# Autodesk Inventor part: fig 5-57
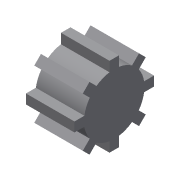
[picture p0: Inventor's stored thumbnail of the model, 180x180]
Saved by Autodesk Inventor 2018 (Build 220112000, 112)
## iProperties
Created: 2005-12
Part Number: fig 5-57
Document SubType Name: Modeling
Designer: CADCIM
Density: 1 g/cm^3
Material: Generic
Appearance: Default
Author: CADCIM
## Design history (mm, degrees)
sketch "Sketch1"
  geometry: C1 r 27.506 at (0, 0)
  constraints: 1 centre point
extrude "Extrusion1" new body sketch "Sketch1" distance "d0" = 20; taper "d1" = 0 deg
sketch "Sketch2"
  geometry: L1 (-12.302, -1.705)-(-16.396, -1.705); L2 (-16.396, -1.705)-(-16.396, 2.216); L3 (-16.396, 2.216)-(-12.302, 2.216); L4 (-7.311, -9.833)-(-10.206, -12.728); L5 (-10.206, -12.728)-(-12.979, -9.955); L6 (-12.979, -9.955)-(-10.084, -7.06); L7 (1.966, -12.051)-(1.966, -16.145); L8 (1.966, -16.145)-(-1.956, -16.145); L9 (-1.956, -16.145)-(-1.956, -12.051); L10 (10.093, -7.06)-(12.988, -9.955); L11 (12.988, -9.955)-(10.215, -12.728); L12 (10.215, -12.728)-(7.32, -9.833); L13 (12.311, 2.216)-(16.405, 2.216); L14 (16.405, 2.216)-(16.405, -1.705); L15 (16.405, -1.705)-(12.311, -1.705); L16 (7.32, 10.344)-(10.215, 13.239); L17 (10.215, 13.239)-(12.988, 10.466); L18 (12.988, 10.466)-(10.093, 7.571); L19 (-1.956, 12.562)-(-1.956, 16.656); L20 (-1.956, 16.656)-(1.966, 16.656); L21 (1.966, 16.656)-(1.966, 12.562); L22 (-10.084, 7.571)-(-12.979, 10.466); L23 (-12.979, 10.466)-(-10.206, 13.239); L24 (-10.206, 13.239)-(-7.311, 10.344); A1 r 12.462 centre (0.005, 0.256) between (-12.302, -1.705) and (-10.084, -7.06); A2 r 12.462 centre (0.005, 0.256) between (-7.311, -9.833) and (-1.956, -12.051); A3 r 12.462 centre (0.005, 0.256) between (1.966, -12.051) and (7.32, -9.833); A4 r 12.462 centre (0.005, 0.256) between (10.093, -7.06) and (12.311, -1.705); A5 r 12.462 centre (0.005, 0.256) between (12.311, 2.216) and (10.093, 7.571); A6 r 12.462 centre (0.005, 0.256) between (7.32, 10.344) and (1.966, 12.562); A7 r 12.462 centre (0.005, 0.256) between (-1.956, 12.562) and (-7.311, 10.344); A8 r 12.462 centre (0.005, 0.256) between (-10.084, 7.571) and (-12.302, 2.216)
  constraints: 48 end point, 16 point on circle, 8 centre point, 2 parallel, 1 horizontal, 1 perpendicular, 57 other
  dimensions: "d4" = 360 deg dimension on A1.centre L2.end (derived)
extrude "Extrusion2" sketch "Sketch2" distance "d6" = 20; taper "d7" = 0 deg
body "Solid1"
